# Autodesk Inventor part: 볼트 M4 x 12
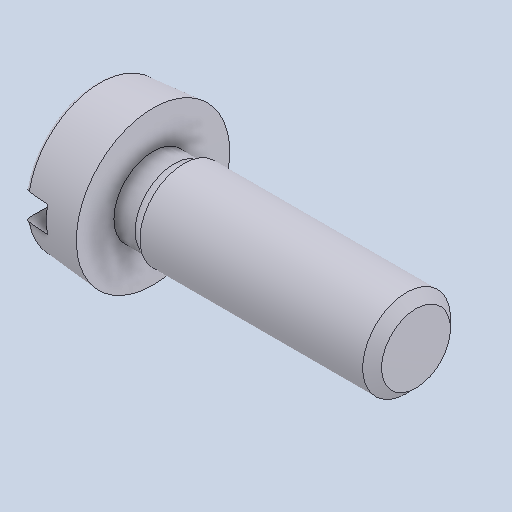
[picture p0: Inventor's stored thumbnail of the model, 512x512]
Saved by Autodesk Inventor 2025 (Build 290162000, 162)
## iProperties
Created: 2024-07
Part Number: 볼트 M4 x 12
Material: 강철, 연강
Description: 6각머리 태핑 나사
Document SubType Name: Modeling
Designer: Administrator
Density: 7.85 g/cm^3
Appearance: 기본값
Author: jhkim
Sending System: Autodesk Inventor 2025
Preprocessor: ST-DEVELOPER v20
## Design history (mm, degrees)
feature "Solid1"
node "솔리드1"
